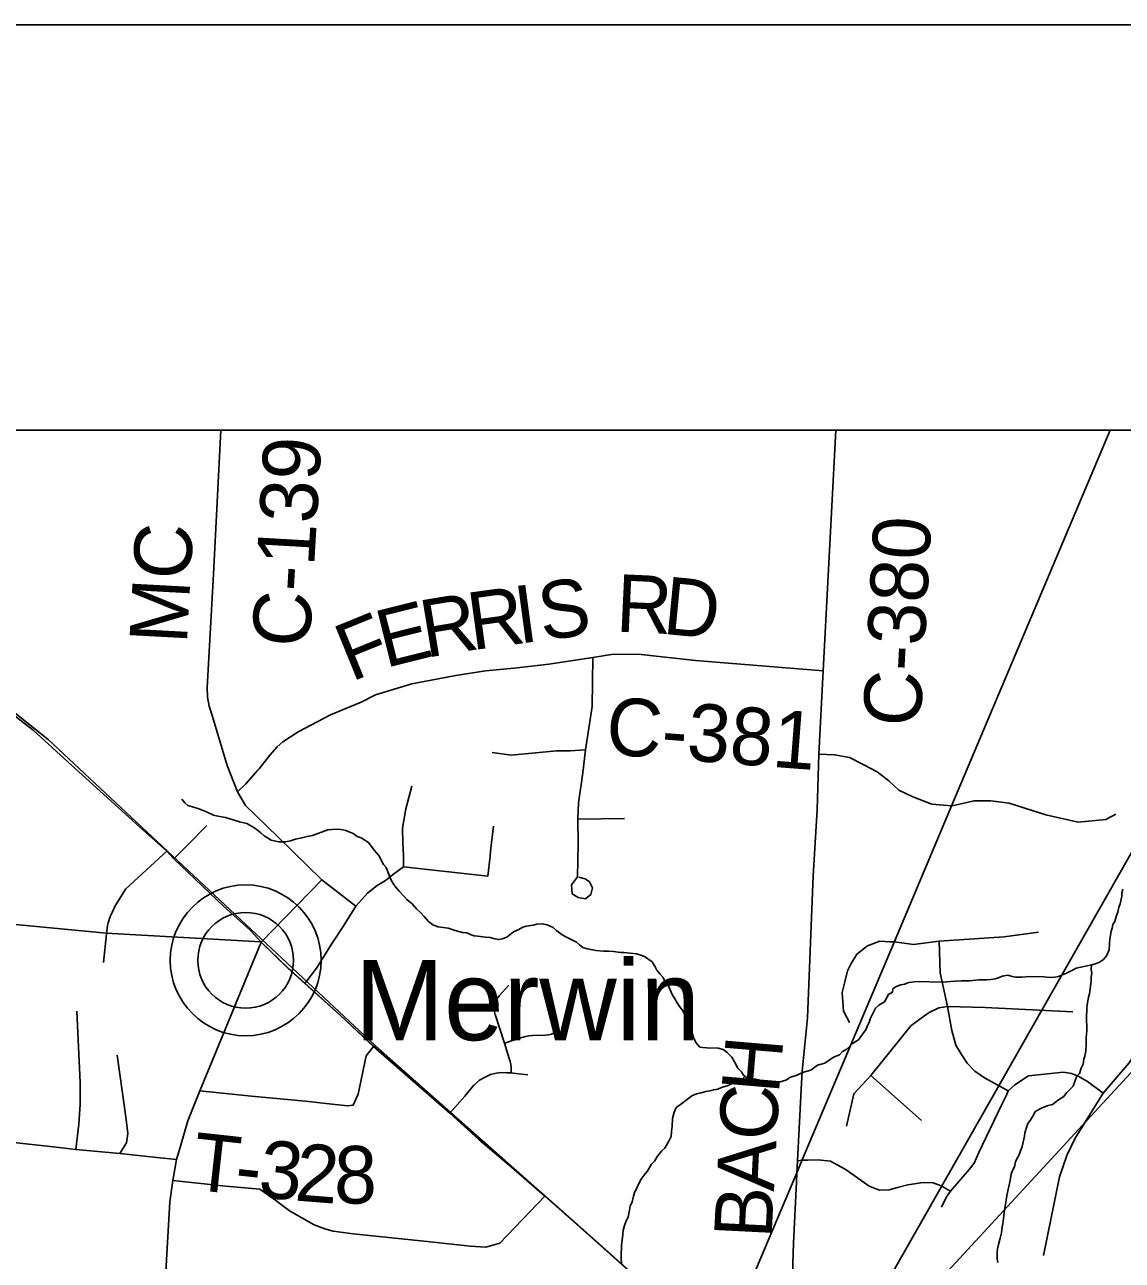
# Model space of a CAD drawing. Extents: x 0 to 39.3, y -3.9 to 22.
# Drawn here: x 2.207 to 3.29, y 19.881 to 21.1 of the extents above; entities that cross this region are included whole.
import ezdxf

# ---------------------------------------------------------------- set-up
doc = ezdxf.new("R2010")
doc.units = 0
for name, color, linetype in [('GM_X_Corporation', 7, 'Continuous'), ('GM_X_County_Road', 7, 'Continuous'), ('GM_X_County_Road_Text', 7, 'Continuous'), ('GM_X_Minor_River', 7, 'Continuous'), ('GM_X_Rail_Line', 7, 'Continuous'), ('GM_X_State_Route', 7, 'Continuous'), ('GM_X_Township_Road', 7, 'Continuous'), ('GM_X_Township_Road_Text', 7, 'Continuous'), ('GM_X_Unincorporated', 7, 'Continuous'), ('GM_X_Unincorporated_Location', 7, 'Continuous'), ('GM_X_Unincorporated_Text', 7, 'Continuous'), ('SH_Data', 7, 'Continuous'), ('SH_Text', 7, 'Continuous')]:
    doc.layers.add(name, color=color, linetype=linetype)

msp = doc.modelspace()

# ---------------------------------------------------------------- linework, layer by layer
at = {"layer": 'GM_X_Corporation'}
for points in [[(2.119, 20.2196), (2.2879, 20.2036), (2.4405, 20.1952), (2.4668, 20.1696), (2.4836, 20.1543), (2.519, 20.1225), (2.5512, 20.0925), (2.5878, 20.0603), (2.6193, 20.0328), (2.6553, 20.0007), (2.6896, 19.9711), (2.7202, 19.9446), (2.7515, 19.9171), (2.8055, 19.8687), (2.8172, 19.8585), (2.8462, 19.8332), (2.8872, 19.7973), (2.8945, 19.7907), (2.9689, 19.967), (2.9744, 19.9801), (3.0652, 20.1955), (3.1219, 20.3298), (3.278, 20.7), (1.9, 20.7)], [(8.7, 20.7), (3.278, 20.7), (3.1219, 20.3298), (3.0652, 20.1955), (2.9744, 19.9801), (2.9689, 19.967), (2.8945, 19.7907)], [(2.8055, 19.8687), (2.7515, 19.9171), (2.7202, 19.9446), (2.6896, 19.9711), (2.6553, 20.0007), (2.6193, 20.0328), (2.5878, 20.0603), (2.5512, 20.0925), (2.519, 20.1225), (2.4836, 20.1543), (2.4668, 20.1696), (2.4405, 20.1952), (2.2879, 20.2036), (2.119, 20.2196)]]:
    msp.add_lwpolyline(points, dxfattribs=at)
at = {"layer": 'GM_X_County_Road'}
for p, q in [((2.3682, 20.2907), (2.3872, 20.3099)), ((2.3547, 20.2769), (2.3682, 20.2907)), ((2.5004, 20.2563), (2.4572, 20.2985)), ((2.4407, 20.1946), (2.5004, 20.2563)), ((2.418, 20.1397), (2.4407, 20.1946)), ((2.4029, 20.1031), (2.418, 20.1397)), ((2.9697, 19.979), (2.9734, 20.0495))]:
    msp.add_line(p, q, dxfattribs=at)
for points in [[(2.3926, 20.4174), (2.3894, 20.4277), (2.3878, 20.4365), (2.3874, 20.4461), (2.3935, 20.5579), (2.401, 20.7)], [(2.9734, 20.0495), (2.9744, 20.0676), (2.9796, 20.1201), (2.9851, 20.2601), (2.9889, 20.3254), (2.9906, 20.3803), (2.9949, 20.4625), (3.0075, 20.7)], [(2.4375, 20.3644), (2.4388, 20.3659), (2.4493, 20.3793), (2.4564, 20.3874), (2.462, 20.3924), (2.4772, 20.4023), (2.5091, 20.4189), (2.5394, 20.4315), (2.5535, 20.4389), (2.5893, 20.4496), (2.6326, 20.458), (2.6619, 20.4625), (2.6901, 20.4652), (2.7243, 20.469), (2.7677, 20.4755), (2.7883, 20.4789), (2.8153, 20.4785), (2.8689, 20.4728), (2.9949, 20.4625)], [(2.4572, 20.2985), (2.4253, 20.3297), (2.4173, 20.3432), (2.4072, 20.3689), (2.3983, 20.3987), (2.3926, 20.4174)], [(2.4173, 20.3432), (2.4257, 20.3511), (2.4375, 20.3644)], [(2.3287, 19.5912), (2.3318, 19.6393), (2.3338, 19.6719), (2.3379, 19.7226), (2.3419, 19.7939), (2.3442, 19.8281), (2.3463, 19.864), (2.3507, 19.9386), (2.3535, 19.9596), (2.3571, 19.9802), (2.3618, 19.9956), (2.3682, 20.0185), (2.3802, 20.0481), (2.4029, 20.1031)], [(2.9687, 19.9584), (2.9691, 19.9665), (2.9697, 19.979)], [(2.9644, 19.857), (2.9656, 19.8977), (2.9687, 19.9584)]]:
    msp.add_lwpolyline(points, dxfattribs=at)
at = {"layer": 'GM_X_Minor_River'}
for points in [[(2.4194, 20.3135), (2.4088, 20.3167), (2.4054, 20.3176), (2.3978, 20.3192), (2.3937, 20.3201), (2.3869, 20.3232), (2.3793, 20.3264), (2.3729, 20.3284), (2.3683, 20.3296), (2.3653, 20.3323), (2.3624, 20.3358)], [(2.8653, 20.108), (2.8631, 20.113), (2.8605, 20.1176), (2.8591, 20.1222), (2.8558, 20.128), (2.8532, 20.1311), (2.8509, 20.1349), (2.8487, 20.1387), (2.8461, 20.143), (2.8421, 20.1522), (2.8391, 20.1553), (2.8373, 20.1599), (2.8343, 20.1633), (2.831, 20.1672), (2.8291, 20.1703), (2.8262, 20.1753), (2.8186, 20.1807), (2.8141, 20.1823), (2.8107, 20.1831), (2.7982, 20.1845), (2.7951, 20.1845), (2.7883, 20.1854), (2.7834, 20.1859), (2.7784, 20.186), (2.7708, 20.1865), (2.7678, 20.1873), (2.7621, 20.1882), (2.758, 20.1894), (2.7546, 20.1921), (2.7516, 20.1948), (2.7452, 20.198), (2.7418, 20.1995), (2.7376, 20.2019), (2.7324, 20.2058), (2.7286, 20.2093), (2.7226, 20.2117), (2.7177, 20.2129), (2.7127, 20.2126), (2.7089, 20.2115), (2.702, 20.2105), (2.6986, 20.2094), (2.6948, 20.2072), (2.6894, 20.205), (2.6829, 20.1998), (2.6783, 20.198), (2.6748, 20.1973), (2.671, 20.1981), (2.6665, 20.1993), (2.6619, 20.1998), (2.6544, 20.2007), (2.6509, 20.2011), (2.6479, 20.2019), (2.6434, 20.2039), (2.6392, 20.2044), (2.632, 20.2064), (2.6252, 20.2084), (2.6154, 20.2097), (2.6101, 20.2117), (2.6059, 20.2148), (2.6015, 20.2199), (2.5977, 20.2241), (2.594, 20.2276), (2.5895, 20.2326), (2.5842, 20.2369), (2.5813, 20.24), (2.5772, 20.2446), (2.5731, 20.2493), (2.5708, 20.2527), (2.5686, 20.2566), (2.5639, 20.2684), (2.5613, 20.2715), (2.5568, 20.2803), (2.552, 20.2854), (2.5464, 20.2931), (2.5393, 20.2977), (2.5355, 20.2989), (2.5314, 20.3021), (2.528, 20.3033), (2.5242, 20.3048), (2.5212, 20.3057), (2.5162, 20.3061), (2.5105, 20.3058), (2.5063, 20.3055), (2.5002, 20.3034), (2.4964, 20.3019), (2.4914, 20.3001), (2.4861, 20.2991), (2.4807, 20.2976), (2.4746, 20.2962), (2.4696, 20.2948), (2.4647, 20.2937), (2.4582, 20.2938), (2.4552, 20.2943), (2.4506, 20.2955), (2.4469, 20.2978), (2.4435, 20.2998), (2.4405, 20.3025), (2.4371, 20.3052), (2.4334, 20.308), (2.4266, 20.3119), (2.4194, 20.3135)], [(3.2904, 20.2469), (3.2896, 20.2435), (3.2895, 20.2401), (3.2879, 20.2325), (3.2867, 20.2291), (3.2855, 20.2242), (3.2839, 20.2201), (3.2827, 20.2151), (3.2807, 20.2121), (3.2799, 20.2087), (3.2791, 20.2057), (3.2782, 20.2012), (3.2778, 20.1981), (3.2773, 20.1932), (3.2769, 20.1871), (3.2745, 20.1811), (3.2714, 20.1777), (3.2675, 20.1751), (3.2637, 20.1733), (3.2599, 20.1722), (3.2538, 20.1712), (3.2446, 20.1691), (3.2408, 20.1672), (3.235, 20.1643), (3.227, 20.161), (3.2236, 20.1603), (3.2186, 20.16), (3.2125, 20.1605), (3.1985, 20.1607), (3.1909, 20.1601), (3.1848, 20.1602), (3.1814, 20.161), (3.1772, 20.1623), (3.1715, 20.1612), (3.168, 20.1594), (3.1646, 20.1587), (3.1604, 20.158), (3.1559, 20.1577), (3.1486, 20.1574), (3.1395, 20.1565), (3.1315, 20.1566), (3.125, 20.1563), (3.1205, 20.156), (3.1125, 20.1554), (3.0866, 20.1559), (3.0824, 20.1552), (3.0794, 20.1548), (3.0752, 20.1534), (3.0714, 20.1527), (3.0668, 20.1509), (3.0637, 20.1487), (3.0633, 20.1453), (3.0594, 20.143), (3.0555, 20.1359), (3.0497, 20.1326), (3.0467, 20.1296), (3.0412, 20.119), (3.0403, 20.1156), (3.0388, 20.1126), (3.0372, 20.1088), (3.0298, 20.0983), (3.024, 20.0946), (3.0182, 20.089), (3.014, 20.0868), (3.0109, 20.0834), (3.0052, 20.0813), (2.9967, 20.0753), (2.9894, 20.0732), (2.9829, 20.0683), (2.9756, 20.0666), (2.9684, 20.0633), (2.9626, 20.0615), (2.958, 20.0585), (2.9515, 20.0567), (2.9466, 20.0553), (2.9435, 20.0561), (2.9284, 20.0594), (2.9231, 20.0599), (2.9193, 20.0611), (2.9163, 20.0634), (2.9144, 20.0669), (2.9107, 20.0704), (2.9077, 20.0761), (2.9048, 20.0811), (2.9003, 20.0858), (2.8962, 20.0889), (2.8913, 20.0901), (2.8799, 20.0903), (2.8764, 20.0907), (2.8734, 20.0912), (2.8693, 20.0958), (2.8671, 20.1008), (2.866, 20.1038), (2.8653, 20.108)], [(3.2595, 20.1722), (3.2594, 20.1677), (3.2598, 20.1642), (3.2593, 20.1604), (3.2593, 20.157), (3.2588, 20.1536), (3.2575, 20.1437), (3.2567, 20.1403), (3.2554, 20.1328), (3.255, 20.1297), (3.2548, 20.1195), (3.255, 20.1103), (3.255, 20.1073), (3.2545, 20.1005), (3.2545, 20.0974), (3.2544, 20.0944), (3.2539, 20.0872), (3.2531, 20.0822), (3.2522, 20.0792), (3.2514, 20.0743), (3.2494, 20.0705), (3.2478, 20.0652), (3.2447, 20.0619), (3.2415, 20.0528), (3.2381, 20.0494), (3.235, 20.0461), (3.2322, 20.0423), (3.2272, 20.0393), (3.2211, 20.0345), (3.2169, 20.0334), (3.2111, 20.0313), (3.2042, 20.0276), (3.2027, 20.0246), (3.1991, 20.0189), (3.1968, 20.0159), (3.1952, 20.011), (3.194, 20.0065), (3.1936, 20.0034), (3.1911, 19.9932), (3.1879, 19.9841), (3.186, 19.9811), (3.1848, 19.9781), (3.1836, 19.9732), (3.1816, 19.9694), (3.1804, 19.9657), (3.1795, 19.9596), (3.1787, 19.9566), (3.1771, 19.9494), (3.1763, 19.946), (3.1754, 19.9406), (3.1745, 19.9338), (3.1737, 19.9304), (3.1732, 19.9247), (3.1723, 19.9167), (3.1715, 19.9137), (3.1707, 19.908), (3.1694, 19.9027), (3.1678, 19.8963), (3.167, 19.8921), (3.1665, 19.8887), (3.1664, 19.8822), (3.1671, 19.8788)], [(2.9177, 20.0623), (2.9135, 20.0578), (2.9089, 20.0567), (2.9044, 20.0549), (2.9013, 20.0534), (2.8948, 20.0513), (2.891, 20.0498), (2.8871, 20.0491), (2.8833, 20.048), (2.8791, 20.0474), (2.8745, 20.0459), (2.87, 20.0452), (2.8654, 20.043), (2.8611, 20.0397), (2.8542, 20.0345), (2.85, 20.0315), (2.848, 20.027), (2.8464, 20.0206), (2.8459, 20.0133), (2.8454, 20.008), (2.8449, 20.0031), (2.843, 19.9989), (2.8387, 19.9914), (2.8356, 19.9884), (2.8317, 19.9836), (2.8286, 19.9787), (2.8258, 19.9757), (2.8215, 19.9685), (2.8181, 19.9644), (2.8153, 19.961), (2.813, 19.9565), (2.811, 19.9512), (2.809, 19.9478), (2.8078, 19.944), (2.8066, 19.9384), (2.8046, 19.9342), (2.8038, 19.9304), (2.8025, 19.9236), (2.8002, 19.9187), (2.799, 19.9153), (2.7978, 19.9104), (2.7973, 19.9058), (2.796, 19.8956), (2.7958, 19.8842), (2.796, 19.8766)]]:
    msp.add_lwpolyline(points, dxfattribs=at)
at = {"layer": 'GM_X_Rail_Line'}
msp.add_lwpolyline([(4.1862, 18.6283), (3.8218, 18.9873), (3.4757, 19.2713), (2.7497, 19.9187), (2.5534, 20.0926), (2.2306, 20.3947), (2.1828, 20.4326), (2.1273, 20.4658), (1.9, 20.5708)], dxfattribs=at)
at = {"layer": 'GM_X_State_Route'}
for points in [[(1.9, 20.5675), (1.9195, 20.5581), (1.9329, 20.553), (1.9462, 20.5471), (1.9753, 20.5324), (2.0079, 20.5169), (2.0242, 20.5099), (2.1015, 20.4762), (2.1252, 20.4643), (2.1518, 20.4513), (2.1684, 20.4407), (2.192, 20.4223), (2.2157, 20.404), (2.2465, 20.3761), (2.282, 20.3436), (2.3207, 20.3084), (2.3475, 20.2844), (2.3547, 20.2769), (2.4035, 20.2301), (2.4299, 20.2065), (2.4407, 20.1946)], [(2.4407, 20.1946), (2.467, 20.1691), (2.4839, 20.1538), (2.5192, 20.122), (2.5514, 20.0919), (2.5881, 20.0598), (2.6266, 20.0259), (2.6555, 20.0001), (2.6898, 19.9706), (2.7204, 19.944), (2.7517, 19.9166), (2.8058, 19.8682), (2.8175, 19.858), (2.8464, 19.8327), (2.8874, 19.7968), (2.8948, 19.7902), (2.9306, 19.7578), (2.9567, 19.7354)]]:
    msp.add_lwpolyline(points, dxfattribs=at)
at = {"layer": 'GM_X_Township_Road'}
for p, q in [((2.7529, 20.316), (2.7989, 20.3168)), ((2.667, 20.2844), (2.6699, 20.3091)), ((2.5812, 20.2691), (2.6641, 20.2599)), ((2.5004, 20.2563), (2.5341, 20.2302)), ((3.0418, 20.063), (3.0919, 20.0187))]:
    msp.add_line(p, q, dxfattribs=at)
for points in [[(2.7677, 20.4755), (2.767, 20.4272), (2.7607, 20.3845), (2.7578, 20.3617), (2.7536, 20.3322), (2.7529, 20.316), (2.7533, 20.2921), (2.7525, 20.2591), (2.7469, 20.2512), (2.7475, 20.2424), (2.7532, 20.2387), (2.7606, 20.2374), (2.7657, 20.2416), (2.7675, 20.2482), (2.7644, 20.2541), (2.7602, 20.2571), (2.7539, 20.2589)], [(2.6684, 20.3819), (2.6874, 20.3792), (2.7321, 20.3836), (2.7455, 20.3836), (2.7607, 20.3845)], [(2.9906, 20.3803), (3.0062, 20.3796), (3.0209, 20.3769), (3.0351, 20.3698), (3.0482, 20.3627), (3.0598, 20.3539), (3.0696, 20.3446), (3.0834, 20.338), (3.102, 20.3309), (3.1135, 20.33)], [(2.5649, 20.2568), (2.5713, 20.2617), (2.5812, 20.2691), (2.5812, 20.2804), (2.5804, 20.2928), (2.5801, 20.3072), (2.5832, 20.3262), (2.5893, 20.3487)], [(3.1135, 20.33), (3.1221, 20.3293), (3.1438, 20.3342), (3.1602, 20.3342), (3.1783, 20.332), (3.1937, 20.327), (3.2146, 20.3204), (3.2463, 20.3132), (3.2737, 20.3156), (3.2837, 20.321)], [(2.2898, 20.2137), (2.2917, 20.2202), (2.2936, 20.224), (2.2968, 20.2307), (2.3073, 20.2475), (2.3475, 20.2844)], [(2.6641, 20.2599), (2.6664, 20.2795), (2.667, 20.2844)], [(2.4839, 20.1538), (2.4954, 20.1691), (2.5108, 20.1937), (2.5216, 20.2103), (2.5341, 20.2302), (2.5456, 20.2432), (2.555, 20.2506), (2.5633, 20.2556), (2.5649, 20.2568)], [(2.2852, 20.1747), (2.2882, 20.2031), (2.289, 20.2111), (2.2898, 20.2137)], [(3.0606, 20.1952), (3.0654, 20.195), (3.084, 20.1923), (3.1095, 20.1958), (3.1734, 20.2001), (3.2073, 20.2047)], [(3.0208, 20.1155), (3.0151, 20.1266), (3.0137, 20.145), (3.0166, 20.1569), (3.0191, 20.1665), (3.0226, 20.1736), (3.0283, 20.1829), (3.0387, 20.1911), (3.0508, 20.1957), (3.0606, 20.1952)], [(3.1773, 20.0481), (3.1541, 20.0607), (3.1444, 20.0674), (3.1371, 20.0754), (3.1313, 20.0839), (3.1258, 20.0931), (3.1217, 20.1075), (3.1176, 20.1314), (3.1103, 20.1645), (3.1095, 20.1958)], [(3.2124, 19.8856), (3.228, 19.9631), (3.2353, 19.9843), (3.2434, 20.0012), (3.271, 20.0458), (3.2966, 20.0755), (3.3142, 20.1022), (3.3238, 20.1177), (3.3309, 20.1327), (3.3304, 20.1511), (3.33, 20.1633)], [(2.6872, 20.0658), (2.6874, 20.0682), (2.6873, 20.0712), (2.687, 20.0741), (2.6863, 20.077), (2.6854, 20.0799), (2.6805, 20.0952), (2.6714, 20.1232), (2.6707, 20.126), (2.6705, 20.1288), (2.6706, 20.1317), (2.6713, 20.1345), (2.6723, 20.1372), (2.6737, 20.1396), (2.6755, 20.1419), (2.6851, 20.1523)], [(3.018, 20.0132), (3.0251, 20.0451), (3.0418, 20.063), (3.0815, 20.1123), (3.0916, 20.1197), (3.0995, 20.1252), (3.1089, 20.1298), (3.1176, 20.1314)], [(3.1176, 20.1314), (3.1546, 20.1302), (3.2411, 20.126)], [(2.258, 19.9903), (2.2609, 20.0151), (2.2621, 20.0348), (2.2623, 20.0561), (2.259, 20.1265)], [(2.6805, 20.0952), (2.6979, 20.1008), (2.7013, 20.1018), (2.7048, 20.1024), (2.7084, 20.1027), (2.7212, 20.1031), (2.7241, 20.1033), (2.7269, 20.104), (2.7296, 20.1051), (2.7321, 20.1065)], [(2.3014, 19.9862), (2.3078, 19.9968), (2.3093, 20.006), (2.3083, 20.0146), (2.3062, 20.0294), (2.2986, 20.0832)], [(2.3802, 20.0481), (2.431, 20.0427), (2.4843, 20.0378), (2.5048, 20.0354), (2.5258, 20.0332), (2.5315, 20.0338), (2.5362, 20.0446), (2.5443, 20.0825), (2.5514, 20.0919)], [(2.6266, 20.0259), (2.6414, 20.0427), (2.6505, 20.0537), (2.656, 20.0586), (2.6611, 20.0611), (2.6668, 20.0641), (2.6723, 20.0654), (2.6778, 20.0662), (2.6829, 20.0658), (2.6864, 20.0658), (2.7037, 20.0639)], [(3.1118, 19.9333), (3.1167, 19.9436), (3.1204, 19.9491), (3.1389, 19.9705), (3.1438, 19.9767), (3.1486, 19.9873), (3.1706, 20.0331), (3.1756, 20.043), (3.1773, 20.0481), (3.1841, 20.0541), (3.1974, 20.0627), (3.2319, 20.0664), (3.2398, 20.065), (3.2466, 20.0624), (3.2557, 20.0572), (3.271, 20.0458)], [(1.9, 20.0439), (2.0231, 20.0187), (2.0539, 20.0123), (2.0684, 20.0107), (2.0979, 20.008), (2.1487, 20.0024), (2.2355, 19.9928), (2.258, 19.9903), (2.3014, 19.9862), (2.3378, 19.9823), (2.3571, 19.9802)], [(2.9697, 19.979), (2.9746, 19.9795), (2.9797, 19.9797)], [(2.9797, 19.9797), (2.99, 19.9799), (3.0021, 19.9787), (3.0161, 19.9712), (3.0177, 19.97)], [(2.7204, 19.944), (2.6759, 19.8978), (2.6624, 19.8937), (2.6467, 19.8948), (2.6045, 19.8993), (2.5314, 19.9068), (2.5117, 19.9095), (2.5036, 19.9119), (2.4929, 19.9158), (2.4687, 19.9297), (2.4552, 19.9398), (2.4395, 19.9509), (2.4057, 19.9541), (2.3535, 19.9596)], [(3.0177, 19.97), (3.0404, 19.954), (3.0506, 19.9501), (3.06, 19.9505), (3.0682, 19.9528), (3.0786, 19.9553), (3.0935, 19.9577), (3.1034, 19.9572), (3.1112, 19.9542), (3.1204, 19.9491)]]:
    msp.add_lwpolyline(points, dxfattribs=at)
at = {"layer": 'GM_X_Unincorporated'}
for radius in [0.0744, 0.0472]:
    msp.add_circle((2.4254, 20.1768), radius, dxfattribs=at)
at = {"layer": 'GM_X_Unincorporated_Location'}
msp.add_line((2.4254, 20.1768), (2.4254, 20.1768), dxfattribs=at)
at = {"layer": 'SH_Data'}
msp.add_lwpolyline([(1.9, 21.1), (9.1, 21.1), (9.1, 13.9), (1.9, 13.9)], close=True, dxfattribs=at)
at = {"layer": 'SH_Text'}
for p, q in [((2.9777, 19.7179), (3.5607, 20.744)), ((2.9781, 19.7184), (3.5607, 20.3507))]:
    msp.add_line(p, q, dxfattribs=at)

# ---------------------------------------------------------------- texts
at = {"layer": 'GM_X_County_Road_Text'}
for s, height, rotation, p in [('C-139', 0.05682, 86.6989, (2.4883, 20.4849)), ('MC', 0.05682, 86.9178, (2.3674, 20.4884)), ('C-380', 0.05682, 86.9579, (3.0908, 20.4065)), ('R', 0.0568, 357.3647, (2.7899, 20.5012)), ('R', 0.0568, 7.8105, (2.6486, 20.4827)), ('I', 0.0568, 7.7117, (2.6948, 20.4891)), ('S', 0.0568, 7.7061, (2.7179, 20.4922)), ('D', 0.0568, 354.4764, (2.8357, 20.4991)), ('E', 0.0568, 14.0737, (2.563, 20.4651)), ('R', 0.0568, 9.3776, (2.603, 20.4752)), ('F', 0.0568, 22.1984, (2.5295, 20.4513)), ('C-381', 0.05682, 355.6213, (2.7794, 20.3804)), ('H', 0.0568, 85.1749, (2.9512, 20.0443)), ('C', 0.0568, 87.0442, (2.9489, 19.9982)), ('A', 0.0568, 87.1501, (2.9464, 19.9483)), ('B', 0.0568, 87.1536, (2.944, 19.9017))]:
    msp.add_text(s, height=height, rotation=rotation, dxfattribs=at).set_placement(p)
at = {"layer": 'GM_X_Township_Road_Text'}
for s, rotation, p in [('T', 353.7048, (2.3708, 19.9508)), ('3', 354.1274, (2.4367, 19.9436)), ('2', 355.4752, (2.4729, 19.9399)), ('8', 359.7677, (2.5125, 19.9369)), ('-', 353.7898, (2.4131, 19.9462))]:
    msp.add_text(s, height=0.0568, rotation=rotation, dxfattribs=at).set_placement(p)
at = {"layer": 'GM_X_Unincorporated_Text'}
msp.add_text('Merwin', height=0.07898, rotation=0, dxfattribs=at).set_placement((2.5331, 20.098))

doc.saveas('drawing.dxf')
